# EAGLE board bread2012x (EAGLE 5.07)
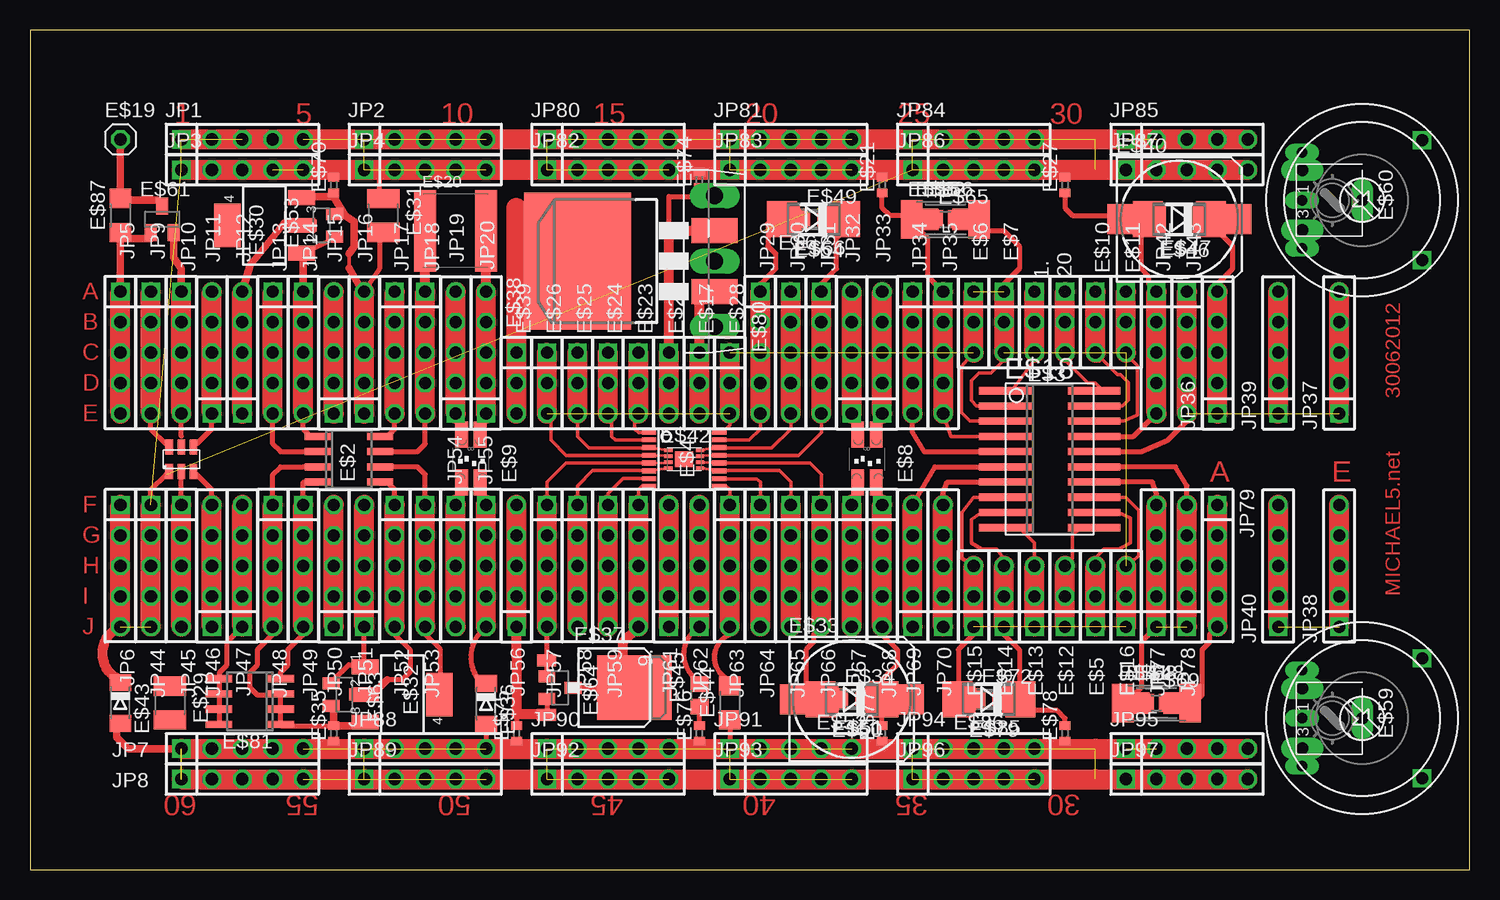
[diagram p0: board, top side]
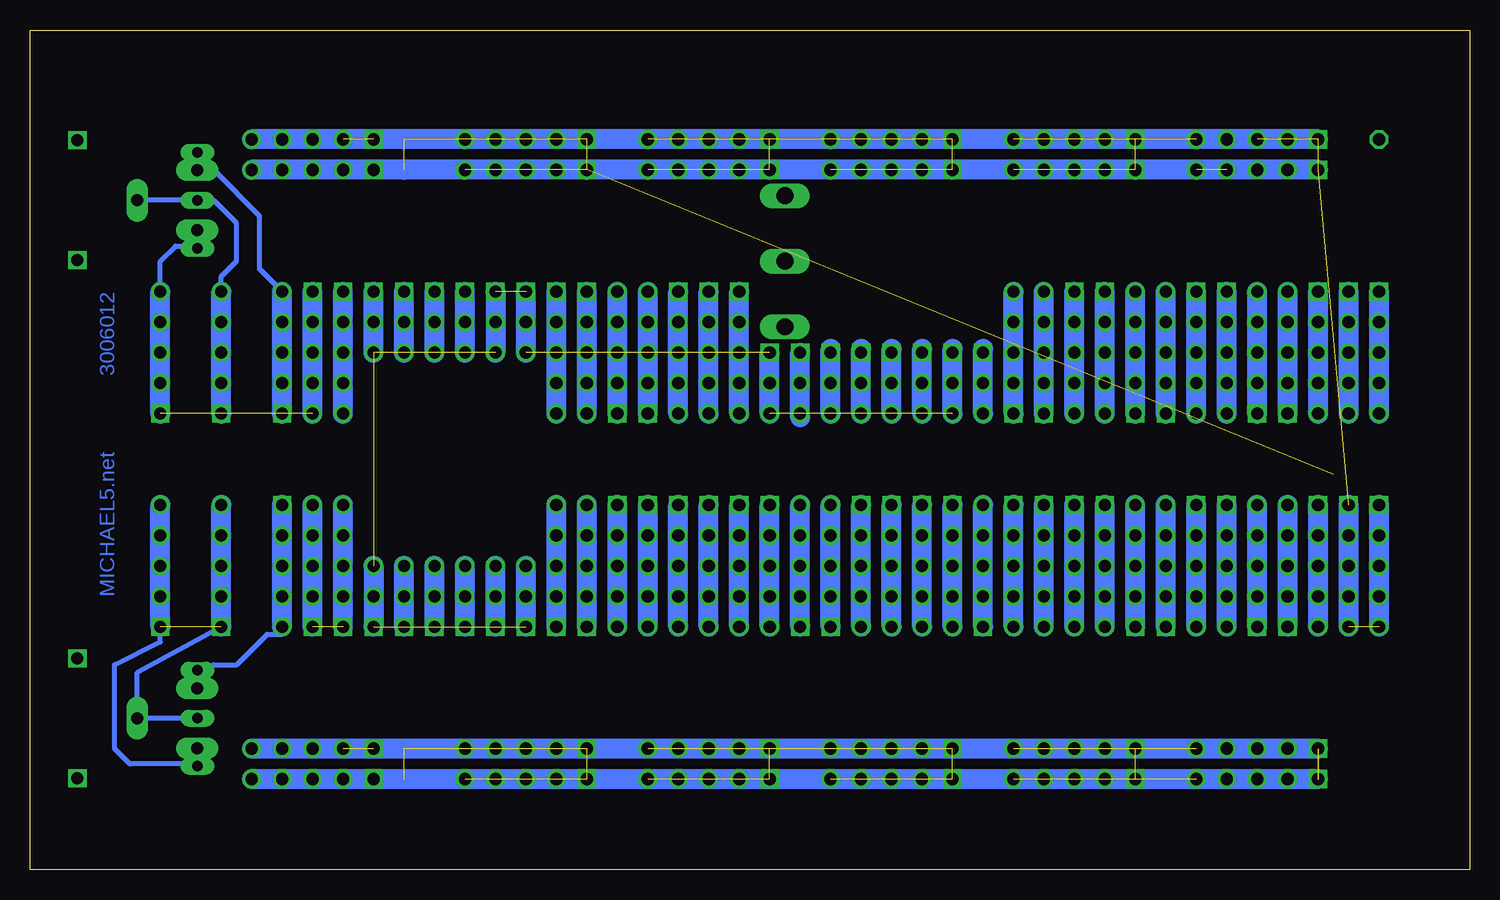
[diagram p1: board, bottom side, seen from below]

Size 120 x 70 mm. Coordinates in mm from the lower left corner, seen from the top.
Outline: 0,0 120,0 120,70 0,70 0,0
Copper layers (1*16): Top 0.035mm / dielectric 1.5mm / Bottom 0.035mm
Design rules "default": minimum track width 10mil, minimum drill 24mil, track to track 8mil, track to pad 8mil, pad to pad 8mil, via to via 8mil, smd to smd 8mil, copper to edge 40mil, drill to drill 8mil, minimum pad ring 10mil, minimum via ring 8mil, stop-mask expansion 4mil, vias tented up to drill 0mil, thermal gap 10mil

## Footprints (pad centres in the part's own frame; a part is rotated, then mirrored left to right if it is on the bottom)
1X03 = drill 1.016 square: 1 -2.54,0 | drill 1.016 octagon: 2 0,0; 3 2.54,0
1X05 = drill 1.016 square: 1 -5.08,0 | drill 1.016 octagon: 2 -2.54,0; 3 0,0; 4 2.54,0; 5 5.08,0
SOT23-6 = smd 0.635 x 1.27: 1 -1.016,-1.016; 2 0,-1.016; 3 1.016,-1.016; 4 1.016,1.016; 5 0,1.016; 6 -1.016,1.016
SO08 = smd 0.6 x 2.2: 1 -1.905,-2.6; 2 -0.635,-2.6; 3 0.635,-2.6; 4 1.905,-2.6; 5 1.905,2.6; 6 0.635,2.6; 7 -0.635,2.6; 8 -1.905,2.6
SO-20 = smd 0.6 x 2.2: 1 -5.715,-2.6; 2 -4.445,-2.6; 3 -3.175,-2.6; 4 -1.905,-2.6; 5 -0.635,-2.6; 6 0.635,-2.6; 7 1.905,-2.6; 8 3.175,-2.6; 9 4.445,-2.6; 10 5.715,-2.6; 11 5.715,2.6; 12 4.445,2.6; 13 3.175,2.6; 14 1.905,2.6; 15 0.635,2.6; 16 -0.635,2.6; 17 -1.905,2.6; 18 -3.175,2.6; 19 -4.445,2.6; 20 -5.715,2.6
SSOP16 = smd 0.4 x 1.2: 1 -2.275,-2.925; 2 -1.625,-2.925; 3 -0.975,-2.925; 4 -0.325,-2.925; 5 0.325,-2.925; 6 0.975,-2.925; 7 1.625,-2.925; 8 2.275,-2.925; 9 2.275,2.925; 10 1.625,2.925; 11 0.975,2.925; 12 0.325,2.925; 13 -0.325,2.925; 14 -0.975,2.925; 15 -1.625,2.925; 16 -2.275,2.925
DUOLEDSMD = smd 1.067 x 2.184: AGRN 0.77,1.95; ARED -0.77,1.95; CGRN 0.77,-2.05; CRED -0.77,-2.05
SO-20WL = smd 0.6 x 2.2: 1 -5.715,-4.788; 2 -4.445,-4.788; 3 -3.175,-4.788; 4 -1.905,-4.788; 5 -0.635,-4.788; 6 0.635,-4.788; 7 1.905,-4.788; 8 3.175,-4.788; 9 4.445,-4.788; 10 5.715,-4.788; 11 5.715,4.788; 12 4.445,4.788; 13 3.175,4.788; 14 1.905,4.788; 15 0.635,4.788; 16 -0.635,4.788; 17 -1.905,4.788; 18 -3.175,4.788; 19 -4.445,4.788; 20 -5.715,4.788
1X01 = drill 1.016 octagon: 1 0,0
C2225K = smd 1.85 x 6.8: 1 -2.55,0; 2 2.55,0
R0402 = smd 0.7 x 0.9: 1 -0.65,0; 2 0.65,0
R1210 = smd 1.6 x 2.7: 1 -1.4,0; 2 1.4,0
SOT223 = smd 1.219 x 2.235: 1 -2.311,-3.099; 2 0,-3.099; 3 2.311,-3.099 | smd 3.6 x 2.2: 4 0,3.099
153CLV-1010 = smd 4 x 2.5: + 4,0; - -4,0
R0805 = smd 1.3 x 1.5: 1 -0.95,0; 2 0.95,0
MINIMELF = smd 1.4 x 1.8: A 1.7,0; C -1.7,0
D-PAK_TO252AA = smd 1 x 1.6: 1 -2.28,-4.8; 3 2.28,-4.8 | smd 5.4 x 6.2: 4 0,2.5
D2PACK = smd 2.083 x 3.81: 1 -2.54,-8.89; 3 2.54,-8.89 | smd 11.43 x 8.89: 2 0,2.54
R5025W = smd 2 x 1.8: 1 -2.311,0; 2 2.311,0
DFN-2X3 = smd 0.7 x 0.3: 1 -1.325,0.75; 2 -1.325,0.25; 3 -1.325,-0.25; 4 -1.325,-0.75; 5 1.325,-0.75; 6 1.325,-0.25; 7 1.325,0.25; 8 1.325,0.75 | smd 1.5 x 1.3: EXP 0,0
R1206 = smd 1.6 x 1.803: 1 -1.422,0; 2 1.422,0
DO-214AC = smd 1.8 x 2.4: A 2.025,0; C -2.025,0
MELF-MLL41 = smd 2.5 x 3: A 2.625,0; C -2.625,0
R3225W = smd 1.8 x 1.8: 1 -1.499,0; 2 1.499,0
SOT23 = smd 1 x 1.4: 1 -0.95,-1.1; 2 0.95,-1.1; 3 0,1.1
RANDL = drill 0.9 long: A -4,5; E 4,5; S 0,5 | drill 1 square: P$1 -5,-5; P$2 5,-5
EVND8AA = drill 1 pad 1.778 long: A -2.5,-2.5; E 2.5,-2.5; S 0,2.5
R2512 = smd 1.8 x 3.2: 1 -2.8,0; 2 2.8,0
R2012 = smd 1.3 x 1.5: 1 -0.85,0; 2 0.85,0
SOT93V = drill 1.397 long: B -5.461,-2.54; C 0,-2.54; E 5.461,-2.54
SO-08 = smd 0.6 x 2.2: 1 -1.905,-2.6; 2 -0.635,-2.6; 3 0.635,-2.6; 4 1.905,-2.6; 5 1.905,2.6; 6 0.635,2.6; 7 -0.635,2.6; 8 -1.905,2.6

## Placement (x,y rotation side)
1.  [1X03]  83.74,45.64 270 top
9.  [1X05]  50.72,25.32 270 top
20  [1X03]  86.28,45.64 270 top
E$1  [SOT23-6]  12.62,34.21 0 top
E$2  [SO08]  26.59,34.21 270 top
E$3  [SO-20]  85.01,34.21 270 top
E$4  [SSOP16]  54.53,34.21 270 top
E$5  [1X03]  88.82,22.78 90 top
E$6  [1X03]  78.66,45.64 270 top
E$7  [1X03]  81.2,45.64 270 top
E$8  [DUOLEDSMD]  69.77,34.21 180 top
E$9  [DUOLEDSMD]  36.75,34.21 180 top
E$10  [1X03]  88.82,45.64 270 top
E$11  [1X03]  91.36,45.64 270 top
E$12  [1X03]  86.28,22.78 90 top
E$13  [1X03]  83.74,22.78 90 top
E$14  [1X03]  81.2,22.78 90 top
E$15  [1X03]  78.66,22.78 90 top
E$16  [1X03]  91.36,22.78 90 top
E$17  [1X03]  55.8,40.56 270 top
E$18  [SO-20WL]  85.01,34.21 270 top
E$19  [1X01]  7.54,60.88 0 top
E$20  [C2225K]  35.48,53.26 0 top
E$21  [R0402]  71.04,57.07 90 top
E$22  [1X03]  53.26,40.56 270 top
E$23  [1X03]  50.72,40.56 270 top
E$24  [1X03]  48.18,40.56 270 top
E$25  [1X03]  45.64,40.56 270 top
E$26  [1X03]  43.1,40.56 270 top
E$27  [R0402]  86.28,57.07 90 top
E$28  [1X03]  58.34,40.56 270 top
E$29  [R1210]  11.67,13.89 270 top
E$30  [SOT223]  19.54,53.7 90 top
E$31  [R1210]  29.45,54.53 270 top
E$32  [SOT223]  31.04,14.59 270 top
E$33  [153CLV-1010]  68.5,14.21 0 top
E$34  [R0805]  68.5,14.21 0 top
E$35  [R0402]  25.32,11.35 90 top
E$36  [MINIMELF]  38.02,13.83 270 top
E$37  [D-PAK_TO252AA]  47.86,15.16 270 top
E$38  [D2PACK]  48.18,50.72 90 top
E$39  [1X03]  40.56,40.56 270 top
E$40  [153CLV-1010]  95.81,54.21 0 top
E$41  [R5025W]  93.9,13.89 0 top
E$42  [DFN-2X3]  54.53,34.21 0 top
E$43  [MINIMELF]  7.54,13.89 270 top
E$44  [R1206]  58.34,13.89 90 top
E$45  [R0805]  55.8,14.53 90 top
E$46  [DO-214AC]  95.81,54.21 180 top
E$47  [MELF-MLL41]  95.81,54.21 180 top
E$48  [R3225W]  93.9,13.89 0 top
E$49  [R0805]  65.33,54.21 0 top
E$50  [DO-214AC]  68.5,14.21 180 top
E$51  [MELF-MLL41]  68.5,14.21 180 top
E$52  [R1206]  68.5,14.21 180 top
E$53  [SOT23]  24.3,53.7 90 top
E$54  [DO-214AC]  65.33,54.21 180 top
E$55  [R5025W]  76.31,54.21 0 top
E$56  [R3225W]  76.31,54.21 0 top
E$57  [RANDL]  111.05,55.8 90 top
E$58  [RANDL]  111.05,12.62 90 top
E$59  [EVND8AA]  108.56,12.62 270 top
E$60  [EVND8AA]  108.56,55.8 270 top
E$61  [SOT23]  11.03,54.21 0 top
E$62  [R2512]  76.31,54.21 0 top
E$63  [SOT23]  26.21,14.59 270 top
E$64  [SOT23]  44.18,15.16 270 top
E$65  [R2012]  76.31,54.21 0 top
E$66  [MELF-MLL41]  65.33,54.21 180 top
E$67  [R1206]  65.33,54.21 180 top
E$68  [R2512]  93.9,13.89 0 top
E$69  [R2012]  93.9,13.89 0 top
E$70  [R0402]  25.32,57.07 90 top
E$72  [R0805]  79.93,14.21 0 top
E$74  [R0402]  55.8,57.51 90 top
E$75  [R0402]  40.56,11.35 90 top
E$76  [R0402]  55.8,11.35 90 top
E$77  [R0402]  71.04,11.35 90 top
E$78  [R0402]  86.28,11.35 90 top
E$79  [DO-214AC]  79.93,14.21 180 top
E$80  [SOT93V]  54.53,50.72 90 top
E$81  [SO-08]  18.34,14.02 90 top
E$85  [MELF-MLL41]  79.93,14.21 180 top
E$86  [R1206]  79.93,14.21 180 top
E$87  [R1206]  7.54,54.53 90 top
JP1  [1X05]  17.7,60.88 0 top
JP2  [1X05]  32.94,60.88 0 top
JP3  [1X05]  17.7,58.34 0 top
JP4  [1X05]  32.94,58.34 0 top
JP5  [1X05]  7.54,43.1 270 top
JP6  [1X05]  7.54,25.32 270 top
JP7  [1X05]  17.7,10.08 0 top
JP8  [1X05]  17.7,7.54 0 top
JP9  [1X05]  10.08,43.1 270 top
JP10  [1X05]  12.62,43.1 270 top
JP11  [1X05]  15.16,43.1 90 top
JP12  [1X05]  17.7,43.1 90 top
JP13  [1X05]  20.24,43.1 270 top
JP14  [1X05]  22.78,43.1 270 top
JP15  [1X05]  25.32,43.1 90 top
JP16  [1X05]  27.86,43.1 90 top
JP17  [1X05]  30.4,43.1 270 top
JP18  [1X05]  32.94,43.1 270 top
JP19  [1X05]  35.48,43.1 90 top
JP20  [1X05]  38.02,43.1 90 top
JP29  [1X05]  60.88,43.1 270 top
JP30  [1X05]  63.42,43.1 270 top
JP31  [1X05]  65.96,43.1 270 top
JP32  [1X05]  68.5,43.1 90 top
JP33  [1X05]  71.04,43.1 90 top
JP34  [1X05]  73.58,43.1 270 top
JP35  [1X05]  76.12,43.1 270 top
JP36  [1X05]  98.98,43.1 90 top
JP37  [1X05]  109.14,43.1 90 top
JP38  [1X05]  109.14,25.32 90 top
JP39  [1X05]  104.06,43.1 90 top
JP40  [1X05]  104.06,25.32 90 top
JP42  [1X05]  93.9,43.1 270 top
JP43  [1X05]  96.44,43.1 270 top
JP44  [1X05]  10.08,25.32 270 top
JP45  [1X05]  12.62,25.32 270 top
JP46  [1X05]  15.16,25.32 90 top
JP47  [1X05]  17.7,25.32 90 top
JP48  [1X05]  20.24,25.32 270 top
JP49  [1X05]  22.78,25.32 270 top
JP50  [1X05]  25.32,25.32 90 top
JP51  [1X05]  27.86,25.32 90 top
JP52  [1X05]  30.4,25.32 270 top
JP53  [1X05]  32.94,25.32 270 top
JP54  [1X05]  35.48,25.32 270 top
JP55  [1X05]  38.02,25.32 270 top
JP56  [1X05]  40.56,25.32 90 top
JP57  [1X05]  43.1,25.32 270 top
JP58  [1X05]  45.64,25.32 270 top
JP59  [1X05]  48.18,25.32 270 top
JP61  [1X05]  53.26,25.32 90 top
JP62  [1X05]  55.8,25.32 90 top
JP63  [1X05]  58.34,25.32 270 top
JP64  [1X05]  60.88,25.32 270 top
JP65  [1X05]  63.42,25.32 270 top
JP66  [1X05]  65.96,25.32 270 top
JP67  [1X05]  68.5,25.32 270 top
JP68  [1X05]  71.04,25.32 270 top
JP69  [1X05]  73.58,25.32 90 top
JP70  [1X05]  76.12,25.32 90 top
JP77  [1X05]  93.9,25.32 90 top
JP78  [1X05]  96.44,25.32 90 top
JP79  [1X05]  98.98,25.32 270 top
JP80  [1X05]  48.18,60.88 0 top
JP81  [1X05]  63.42,60.88 0 top
JP82  [1X05]  48.18,58.34 0 top
JP83  [1X05]  63.42,58.34 0 top
JP84  [1X05]  78.66,60.88 0 top
JP85  [1X05]  96.44,60.88 0 top
JP86  [1X05]  78.66,58.34 0 top
JP87  [1X05]  96.44,58.34 0 top
JP88  [1X05]  32.94,10.08 0 top
JP89  [1X05]  32.94,7.54 0 top
JP90  [1X05]  48.18,10.08 0 top
JP91  [1X05]  63.42,10.08 0 top
JP92  [1X05]  48.18,7.54 0 top
JP93  [1X05]  63.42,7.54 0 top
JP94  [1X05]  78.66,10.08 0 top
JP95  [1X05]  96.44,10.08 0 top
JP96  [1X05]  78.66,7.54 0 top
JP97  [1X05]  96.44,7.54 0 top

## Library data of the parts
1. 9. 20 E$5-E$7 E$10-E$17 E$22-E$26 E$28 E$39 JP1-JP20 JP29-JP40 JP42-JP59 JP61-JP70 JP77-JP97 = pinhead(2)
E$1 = microchip-5
E$2 E$4 = linear
E$3 E$18 E$42 = microchip
E$8 E$9 = led
E$19 = pinhead
E$20 E$21 E$27 E$29 E$31 E$33-E$35 E$40 E$41 E$44 E$45 E$48 E$49 E$52 E$55 E$56 E$62 E$65 E$67-E$70 E$72 E$74-E$78 E$86 E$87 = rcl
E$30 E$32 E$53 E$61 E$63 E$64 = transistor-npn
E$36 E$43 E$46 E$47 E$50 E$51 E$54 E$66 E$79 E$85 = diode
E$37 E$38 E$80 E$81 = transistor-power
E$57-E$60 = pot

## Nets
N$1: JP1.1 JP1.2 JP1.3
N$2: JP2.1 JP2.2
N$3: JP3.4 JP3.5
N$76: JP80.1 JP80.2 JP80.3
N$77: JP81.1 JP81.2
N$78: JP82.4 JP82.5
N$80: JP84.1 JP84.2 JP84.3
N$81: JP85.1 JP85.2
N$82: JP86.4 JP86.5
N$84: JP88.1 JP88.2
N$86: JP90.1 JP90.2 JP90.3
N$87: JP91.1 JP91.2
N$88: JP92.4 JP92.5
N$90: JP94.1 JP94.2 JP94.3
N$91: JP95.1 JP95.2
N$92: JP96.4 JP96.5
S$30: E$7.3
S$43: E$14.3
S$45: E$17.1
S$57: E$19.1

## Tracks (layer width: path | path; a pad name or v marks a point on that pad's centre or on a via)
N$1  (2 unrouted)
N$2  (1 unrouted)
N$3  (1 unrouted)
N$4
  Top 1.676: 7.54,38.02 7.54,48.18
N$5
  Top 0.406: 11.35,35.48 10.08,36.75 10.08,38.02
  Top 1.676: 10.08,38.02 10.08,48.18
N$6
  Top 0.406: 12.62,36.11 12.62,38.02
  Top 1.676: 12.62,38.02 12.62,48.18
N$7  (1 unrouted)
  Top 1.676: 109.14,38.02 109.14,48.18 | 104.06,38.02 104.06,48.18
N$8
  Top 1.676: 93.9,38.02 93.9,48.18
N$15
  Top 0.305: 76.44,42.15 76.12,42.47 76.12,43.1 | 79.3,36.11 76.75,36.11 76.12,38.02
  Top 0.406: 76.75,39.29 76.44,42.15 | 76.12,48.18 74.85,49.45 74.85,52.62 73.58,53.9 73.58,54.53 71.67,54.53 71.04,55.16 71.04,56.44
  Top 1.676: 76.12,38.02 76.12,43.1 76.12,48.18
N$19
  Top 0.406: 65.96,48.18 65.96,48.81 67.23,50.09 67.23,52.62 67.87,53.26 67.87,54.53
  Top 1.676: 65.96,38.02 65.96,48.18
N$20
  Top 0.305: 57.7,35.16 61.83,35.16 63.42,36.75 63.42,38.02
  Top 1.676: 63.42,38.02 63.42,48.18
N$21
  Top 0.305: 57.7,35.8 59.93,35.8 60.88,36.75 60.88,38.02
  Top 0.406: 61.52,53.9 61.52,51.99 62.15,51.35 62.15,50.09 60.88,48.81 60.88,46.91
  Top 1.676: 60.88,38.02 60.88,46.91 60.88,48.18
N$25
  Top 0.305: 51.04,36.43 50.72,36.43 50.4,36.75 50.4,37.7 50.72,38.02
N$26
  Top 0.305: 51.04,35.8 48.81,35.8 48.5,36.11 48.5,37.7 48.18,38.02
N$27
  Top 0.305: 51.04,35.16 46.59,35.16 45.64,36.11 45.64,38.02
N$28
  Top 0.305: 51.35,34.53 44.69,34.53 43.42,35.8 43.42,37.7 43.1,38.02
N$29
  Top 1.676: 40.56,38.02 40.56,55.16
N$30
  Top 0.813: 38.02,48.18 38.02,50.72
  Top 1.676: 38.02,38.02 38.02,48.18
N$31
  Top 1.676: 35.48,38.02 35.48,48.18
N$32
  Top 0.406: 29.77,34.84 32.3,34.84 32.94,35.48 32.94,38.02
  Top 0.813: 32.94,48.18 32.94,51.04
  Top 1.676: 32.94,38.02 32.94,48.18
N$33
  Top 0.406: 29.77,36.11 30.4,36.75 30.4,38.02
  Top 1.676: 30.4,38.02 30.4,48.18
N$34
  Top 0.305: 26.59,50.15 26.59,51.35
  Top 0.406: 29.13,52.62 29.13,50.09 27.86,48.18
  Top 0.61: 22.46,56.12 25.32,56.12 26.27,54.53 27.04,54.02 27.04,51.93 26.59,51.35 | 26.59,50.15 27.54,48.5 27.86,48.18
  Top 1.676: 27.86,38.02 27.86,48.18
N$35
  Top 1.676: 25.32,38.02 25.32,48.18
N$36
  Top 0.406: 23.41,36.11 22.78,36.75 22.78,38.02
  Top 1.676: 22.78,38.02 22.78,48.18
N$37
  Top 0.406: 23.41,34.84 20.88,34.84 20.24,35.48 20.24,38.02
  Top 1.676: 20.24,38.02 20.24,48.18
N$38
  Top 0.61: 22.14,53.9 21.19,53.9 18.34,50.4 17.7,48.18
  Top 1.676: 17.7,38.02 17.7,48.18
N$39
  Top 0.406: 13.89,35.48 15.16,36.75 15.16,38.02
  Top 1.676: 15.16,38.02 15.16,48.18
N$40  (4 unrouted)
  Top 0.406: 11.35,32.94 10.08,31.67 10.08,30.4
  Top 1.676: 88.82,58.34 101.52,58.34 | 88.82,60.88 101.52,60.88 | 73.58,60.88 83.74,60.88 | 73.58,58.34 83.74,58.34 | 10.08,20.24 10.08,30.4
N$41
  Top 0.406: 97.08,13.89 97.71,14.53 97.71,18.34 98.34,18.97 98.34,19.61 98.98,20.24
  Top 1.676: 98.98,20.24 98.98,30.4
N$42
  Top 0.406: 90.41,33.58 95.49,33.58 96.44,31.99 96.44,30.08
  Top 1.676: 96.44,30.4 96.44,30.08 96.44,20.24
N$43
  Top 0.406: 90.41,32.3 93.58,32.3 93.9,31.35 93.9,30.4
  Top 1.676: 93.9,20.24 93.9,30.4
N$49
  Top 0.813: 7.54,15.79 arc-136 7.54,20.24
N$50
  Top 0.305: 76.12,30.4 76.12,30.72
  Top 0.406: 79.93,32.3 76.44,32.3 76.12,31.35 76.12,30.72
  Top 1.676: 76.12,20.24 76.12,30.4
N$51
  Top 0.406: 79.93,33.58 75.42,33.58 73.58,30.4
  Top 1.676: 73.58,20.24 73.58,30.4
N$52
  Top 0.406: 71.04,20.24 71.04,19.61 72.31,18.34 72.31,17.06 71.04,15.79 71.04,14.53
  Top 1.676: 71.04,20.24 71.04,30.4
N$53
  Top 1.676: 68.5,20.24 68.5,30.4
N$54
  Top 1.676: 65.96,20.24 65.96,30.4
N$55
  Top 0.305: 57.39,33.26 62.47,33.26 63.42,32.3 63.42,30.4
  Top 1.676: 63.42,20.24 63.42,30.4
N$56
  Top 0.305: 57.7,32.56 60.56,32.56 60.88,32.3 60.88,30.4
  Top 1.676: 60.88,20.24 60.88,30.4
N$57
  Top 0.305: 58.02,31.99 58.34,31.67 58.34,30.08
  Top 1.676: 58.34,20.24 58.34,30.08 58.34,30.4
N$58
  Top 0.406: 55.93,15.6 arc-121 55.8,20.24
  Top 1.676: 55.8,20.24 55.8,30.4
N$59
  Top 1.676: 53.26,20.24 53.26,30.4
N$60
  Top 0.305: 51.35,31.99 51.04,31.99 50.72,31.67 50.72,30.4
  Top 0.406: 45.64,15.16 49.45,15.16
  Top 0.813: 49.45,15.16 49.45,18.97 50.72,20.24
  Top 1.676: 50.72,20.24 50.72,30.4
N$61
  Top 0.305: 51.04,32.62 49.45,32.62 48.18,31.35 48.18,30.4
  Top 1.676: 48.18,20.24 48.18,30.4
N$62
  Top 0.305: 51.04,33.26 46.91,33.26 45.64,31.99 45.64,30.4
  Top 1.676: 45.64,20.24 45.64,30.4
N$63
  Top 0.305: 51.04,33.89 44.69,33.89 43.1,32.3 43.1,30.4
  Top 0.406: 43.1,17.7 43.1,20.24
  Top 1.676: 43.1,20.24 43.1,30.4
N$64
  Top 1.676: 40.56,20.24 40.56,30.4
N$65
  Top 0.406: 38.02,20.24 arc106 38.02,15.16
  Top 1.676: 38.02,20.24 38.02,30.4
N$66
  Top 1.676: 35.48,20.24 35.48,30.4
N$67
  Top 0.406: 29.77,33.58 32.3,33.58 32.94,32.94 32.94,30.4 | 34.21,16.43 34.21,18.34 32.94,19.61 32.94,20.24
  Top 1.676: 32.94,20.24 32.94,30.4
N$68
  Top 0.406: 29.77,32.3 30.4,31.67 30.4,30.4
  Top 1.676: 30.4,20.24 30.4,30.4
N$69
  Top 0.406: 25.32,15.79 26.59,17.06 27.86,17.06 27.86,20.24
  Top 1.676: 27.86,20.24 27.86,30.4
N$70
  Top 1.676: 25.32,20.24 25.32,30.4
N$71
  Top 0.406: 22.78,30.4 22.78,32.3 | 20.88,15.79 20.88,16.43 21.51,17.06 21.51,18.34 22.78,19.61 22.78,20.24
  Top 1.676: 22.78,20.24 22.78,30.4
N$72
  Top 0.406: 22.78,33.58 20.88,33.58 20.24,32.94 20.24,30.4 | 20.24,14.53 18.97,14.53 18.34,15.16 18.34,16.43 18.97,17.06 18.97,18.34 20.24,19.61 20.24,20.24
  Top 1.676: 20.24,20.24 20.24,30.4
N$73
  Top 0.406: 15.79,11.98 15.79,16.43 16.43,17.06 16.43,18.97 17.7,20.24
  Top 1.676: 17.7,20.24 17.7,30.4
N$74
  Top 0.406: 13.89,32.94 15.16,31.67 15.16,30.4
  Top 1.676: 15.16,20.24 15.16,30.4
N$75
  Top 0.406: 12.62,30.4 12.62,32.94
  Top 1.676: 12.62,20.24 12.62,30.4
N$76  (2 unrouted)
N$77  (1 unrouted)
N$78  (1 unrouted)
N$79  (3 unrouted)
  Top 1.676: 58.34,60.88 68.5,60.88 | 58.34,58.34 68.5,58.34 | 43.1,58.34 53.26,58.34 | 43.1,60.88 53.26,60.88
N$80  (2 unrouted)
N$81  (1 unrouted)
N$82  (1 unrouted)
N$83  (3 unrouted)
  Top 0.406: 29.13,56.44 29.13,58.34
  Top 1.676: 27.86,60.88 38.02,60.88 | 27.86,58.34 29.13,58.34 38.02,58.34 | 12.62,58.34 22.78,58.34 | 12.62,60.88 22.78,60.88
N$84  (1 unrouted)
N$85  (3 unrouted)
  Top 1.676: 73.58,7.54 83.74,7.54 | 73.58,10.08 83.74,10.08 | 88.82,10.08 101.52,10.08 | 88.82,7.54 101.52,7.54
N$86  (2 unrouted)
N$87  (1 unrouted)
N$88  (1 unrouted)
N$89  (3 unrouted)
  Top 1.676: 58.34,10.08 68.5,10.08 | 58.34,7.54 68.5,7.54 | 43.1,7.54 53.26,7.54 | 43.1,10.08 53.26,10.08
N$90  (2 unrouted)
N$91  (1 unrouted)
N$92  (1 unrouted)
N$94
  Bottom 1.676: 7.54,38.02 7.54,48.18
N$95
  Bottom 1.676: 10.08,38.02 10.08,48.18
N$96
  Bottom 1.676: 12.62,38.02 12.62,48.18
N$97
  Bottom 1.676: 15.16,38.02 15.16,48.18
N$98
  Bottom 1.676: 17.7,38.02 17.7,48.18
N$99
  Bottom 1.676: 20.24,38.02 20.24,48.18
N$100
  Bottom 1.676: 22.78,38.02 22.78,48.18
N$101
  Bottom 1.676: 25.32,38.02 25.32,48.18
N$102
  Bottom 1.676: 27.86,38.02 27.86,48.18
N$103
  Bottom 1.676: 30.4,38.02 30.4,48.18
N$104
  Bottom 1.676: 32.94,38.02 32.94,48.18
N$105
  Bottom 1.676: 35.48,38.02 35.48,48.18
N$106
  Bottom 1.676: 38.02,38.02 38.02,48.18
N$107
  Bottom 1.676: 40.56,38.02 40.56,43.42
N$108
  Bottom 1.676: 43.1,38.02 43.1,43.42
N$109
  Bottom 1.676: 45.64,38.02 45.64,43.42
N$110
  Bottom 1.676: 48.18,38.02 48.18,43.42
N$111
  Bottom 1.676: 50.72,38.02 50.72,43.42
N$112
  Bottom 1.676: 53.26,38.02 53.26,43.42
N$113
  Bottom 1.676: 55.8,37.7 55.8,43.1
N$114
  Bottom 1.676: 58.34,38.02 58.34,43.04
N$115
  Bottom 1.676: 60.88,38.02 60.88,48.18
N$116
  Bottom 1.676: 63.42,38.02 63.42,48.18
N$117
  Bottom 1.676: 65.96,38.02 65.96,48.18
N$118
  Bottom 1.676: 68.5,38.02 68.5,48.18
N$119
  Bottom 1.676: 71.04,38.02 71.04,48.18
N$120
  Bottom 1.676: 73.58,38.02 73.58,48.18
N$121
  Bottom 1.676: 76.12,38.02 76.12,48.18
N$126
  Top 0.406: 40.56,12.94 40.56,11.98
  Top 0.813: 40.56,20.24 40.56,17.7 40.56,12.94 42.34,12.94
N$128
  Bottom 1.676: 93.9,38.02 93.9,48.18
N$130  (5 unrouted)
  Bottom 1.676: 10.08,20.24 10.08,30.4 | 12.62,60.88 22.78,60.88 | 12.62,58.34 22.78,58.34 | 27.86,58.34 38.02,58.34 | 27.86,60.88 38.02,60.88 | 7.54,20.24 7.54,30.4
N$131
  Bottom 1.676: 12.62,20.24 12.62,30.4
N$132
  Bottom 1.676: 15.16,20.24 15.16,30.4
N$133
  Bottom 1.676: 17.7,20.24 17.7,30.4
N$134
  Bottom 1.676: 20.24,20.24 20.24,30.4
N$135
  Bottom 1.676: 22.78,20.24 22.78,30.4
N$136
  Bottom 1.676: 25.32,20.24 25.32,30.4
N$137
  Bottom 1.676: 27.86,20.24 27.86,30.4
N$138
  Bottom 1.676: 30.4,20.24 30.4,30.4
N$139
  Bottom 1.676: 32.94,20.24 32.94,30.4
N$140
  Bottom 1.676: 35.48,20.24 35.48,30.4
N$141
  Bottom 1.676: 38.02,20.24 38.02,30.4
N$142
  Bottom 1.676: 40.56,20.24 40.56,30.4
N$143
  Bottom 1.676: 43.1,20.24 43.1,30.4
N$144
  Bottom 1.676: 45.64,20.24 45.64,30.4
N$145
  Bottom 1.676: 48.18,20.24 48.18,30.4
N$146
  Bottom 1.676: 50.72,20.24 50.72,30.4
N$147
  Bottom 1.676: 53.26,20.24 53.26,30.4
N$148
  Bottom 1.676: 55.8,20.24 55.8,30.4
N$149
  Bottom 1.676: 58.34,20.24 58.34,30.4
N$150
  Bottom 1.676: 60.88,20.24 60.88,30.4
N$151
  Bottom 1.676: 63.42,20.24 63.42,30.4
N$152
  Bottom 1.676: 65.96,20.24 65.96,30.4
N$153
  Bottom 1.676: 68.5,20.24 68.5,30.4
N$154
  Bottom 1.676: 71.04,20.24 71.04,30.4
N$155
  Bottom 1.676: 73.58,20.24 73.58,30.4
N$156
  Bottom 1.676: 76.12,20.24 76.12,30.4
N$164  (1 unrouted)
  Bottom 1.676: 96.44,20.24 96.44,30.4 | 93.9,20.24 93.9,30.4
N$165
  Bottom 0.406: 98.98,20.24 98.98,19.61 100.25,19.61 102.79,17.06 104.69,17.06 105.97,16.43
  Bottom 1.676: 98.98,20.24 98.98,30.4
N$166  (3 unrouted)
  Bottom 1.676: 43.1,60.88 53.26,60.88 | 43.1,58.34 53.26,58.34 | 58.34,58.34 68.5,58.34 | 58.34,60.88 68.5,60.88
N$167  (3 unrouted)
  Bottom 1.676: 73.58,60.88 83.74,60.88 | 73.58,58.34 83.74,58.34 | 88.82,58.34 101.52,58.34 | 88.82,60.88 101.52,60.88
N$168  (3 unrouted)
  Bottom 1.676: 27.86,7.54 38.02,7.54 | 27.86,10.08 38.02,10.08 | 12.62,10.08 22.78,10.08 | 12.62,7.54 22.78,7.54
N$169  (3 unrouted)
  Bottom 1.676: 43.1,10.08 53.26,10.08 | 43.1,7.54 53.26,7.54 | 58.34,7.54 68.5,7.54 | 58.34,10.08 68.5,10.08
N$170  (3 unrouted)
  Bottom 1.676: 73.58,10.08 83.74,10.08 | 73.58,7.54 83.74,7.54 | 88.82,7.54 101.52,7.54 | 88.82,10.08 101.52,10.08
N$191  (1 unrouted)
  Top 1.676: 104.06,20.24 104.06,30.4 | 109.14,20.24 109.14,30.4
N$192
  Bottom 0.406: 109.14,20.24 109.14,18.97 112.95,17.06 112.95,10.08 111.68,8.81 106.6,8.81
  Bottom 1.676: 109.14,20.24 109.14,30.4
N$193
  Top 0.406: 44.37,54.53 45.01,54.53 45.64,53.9 45.64,51.35
N$194
  Top 0.406: 43.1,48.18 43.1,51.99
S$1
  Top 1.676: 83.74,60.88 88.82,60.88
S$2
  Top 1.676: 83.74,58.34 88.82,58.34
S$3  (1 unrouted)
  Top 1.676: 53.26,60.88 58.34,60.88 | 68.5,60.88 73.58,60.88
S$4  (1 unrouted)
  Top 1.676: 53.26,58.34 58.34,58.34 | 68.5,58.34 73.58,58.34
S$5  (1 unrouted)
  Top 1.676: 22.78,60.88 27.86,60.88 | 38.02,60.88 43.1,60.88
S$6  (1 unrouted)
  Top 1.676: 22.78,58.34 27.86,58.34 | 38.02,58.34 43.1,58.34
S$7
  Top 1.676: 83.74,10.08 88.82,10.08
S$8
  Top 1.676: 83.74,7.54 88.82,7.54
S$9  (1 unrouted)
  Top 1.676: 53.26,10.08 58.34,10.08 | 68.5,10.08 73.58,10.08
S$10  (1 unrouted)
  Top 1.676: 53.26,7.54 58.34,7.54 | 68.5,7.54 73.58,7.54
S$11  (1 unrouted)
  Top 1.676: 22.78,10.08 27.86,10.08 | 38.02,10.08 43.1,10.08
S$12  (1 unrouted)
  Top 1.676: 22.78,7.54 27.86,7.54 | 38.02,7.54 43.1,7.54
S$13
  Bottom 1.676: 22.78,60.88 27.86,60.88
S$14
  Bottom 1.676: 22.78,58.34 27.86,58.34
S$15  (1 unrouted)
  Bottom 1.676: 53.26,60.88 58.34,60.88 | 38.02,60.88 43.1,60.88
S$16  (1 unrouted)
  Bottom 1.676: 53.26,58.34 58.34,58.34 | 38.02,58.34 43.1,58.34
S$17  (1 unrouted)
  Bottom 1.676: 83.74,60.88 88.82,60.88 | 68.5,60.88 73.58,60.88
S$18  (1 unrouted)
  Bottom 1.676: 83.74,58.34 88.82,58.34 | 68.5,58.34 73.58,58.34
S$19
  Bottom 1.676: 22.78,10.08 27.86,10.08
S$20
  Bottom 1.676: 22.78,7.54 27.86,7.54
S$21  (1 unrouted)
  Bottom 1.676: 53.26,10.08 58.34,10.08 | 38.02,10.08 43.1,10.08
S$22  (1 unrouted)
  Bottom 1.676: 53.26,7.54 58.34,7.54 | 38.02,7.54 43.1,7.54
S$23  (1 unrouted)
  Bottom 1.676: 83.74,10.08 88.82,10.08 | 68.5,10.08 73.58,10.08
S$24  (1 unrouted)
  Bottom 1.676: 83.74,7.54 88.82,7.54 | 68.5,7.54 73.58,7.54
S$26
  Top 1.676: 71.04,38.02 71.04,48.18
S$27
  Top 0.305: 68.5,48.18 68.18,47.86
  Top 1.676: 68.5,38.02 68.5,48.18
S$29
  Top 0.305: 57.7,36.43 58.34,37.07 58.34,37.7 58.66,38.02
S$30
  Top 0.406: 81.52,42.78 E$7.3
S$32
  Top 0.305: 57.7,34.53 64.06,34.53 65.96,36.43 65.96,37.7
S$33
  Top 0.305: 57.7,33.89 65.01,33.89 65.96,32.94 65.96,30.72
S$34  (3 unrouted)
  Bottom 0.406: 104.69,58.34 100.89,54.53 100.89,50.09 98.98,48.18 | 111.05,55.8 104.69,55.8 102.79,53.9 102.79,50.72 104.06,49.45 104.06,48.18 | 105.97,51.99 107.87,51.99 109.14,50.72 109.14,48.18
  Bottom 1.676: 109.14,38.02 109.14,48.18 | 98.98,38.02 98.98,48.18 | 96.44,38.02 96.44,48.18 | 104.06,38.02 104.06,48.18
S$35
  Top 0.406: 88.82,42.78 89.14,42.47
S$37
  Top 0.406: 90.41,36.11 92,36.11 93.58,37.7
S$38
  Bottom 0.406: 106.6,12.62 111.05,12.62 111.05,16.43 104.06,20.24
  Bottom 1.676: 104.06,20.24 104.06,30.4
S$39
  Top 0.305: 96.12,31.04 96.44,30.72
S$40
  Top 0.406: 30.4,19.61 31.67,18.34 31.67,16.43 31.04,15.79 29.77,15.79
  Top 0.61: 29.77,15.79 28.5,14.53 27.23,14.53
S$41
  Top 0.406: 20.88,14.53 20.88,11.98 25.32,11.98
  Top 0.61: 25.32,13.26 25.32,11.98 27.67,11.98
S$42  (30 unrouted)
  Top 0.305: 90.09,39.92 89.45,39.92 88.82,40.56 88.19,40.56 86.28,42.47 86.28,43.1 | 90.72,38.66 91.04,38.66 91.55,39.16 91.55,40.62 90.92,41.26 90.66,41.26 88.82,43.1 | 90.72,37.38 91.17,37.38 92.31,37.89 92.31,42.02 91.68,42.66 91.68,42.78 91.36,43.1 | 81.83,39.92 83.74,42.47 83.74,43.1 | 79.3,38.66 78.91,38.66 78.47,39.1 78.47,40.75 79.11,41.39 80.12,41.39 81.2,42.47 81.2,43.1 | 79.3,37.38 78.34,37.38 77.64,38.08 77.64,41.96 78.66,43.1 | 79.3,31.04 78.66,31.04 77.71,29.77 77.71,25.95 78.66,25.32 | 79.3,29.77 78.47,29.19 78.47,27.23 79.3,26.72 80.56,26.72 81.2,25.95 81.2,25.32 | 82.47,28.5 83.74,27.23 83.74,25.32 | 90.72,31.04 91.36,31.04 92.44,29.96 92.44,26.14 91.36,25.32 | 90.72,29.77 91.74,29.32 91.74,27.23 90.79,26.72 89.52,26.72 88.82,25.95 88.82,25.32 | 86.28,25.32 86.92,25.95 86.92,27.86 87.55,28.5
  Top 0.406: 77.39,14.53 77.39,18.34 78.66,19.61 78.66,20.24 | 91.36,20.24 91.36,19.61 | 79.93,53.26 81.2,53.26 82.47,51.99 82.47,50.09 81.2,48.81 81.2,48.18
  Top 1.676: 78.66,20.24 78.66,25.32 | 81.2,20.24 81.2,25.32 | 83.74,20.24 83.74,25.32 | 86.28,20.24 86.28,25.32 | 88.82,20.24 88.82,25.32 | 91.36,25.32 91.36,20.24 | 91.36,43.1 91.36,48.18 | 88.82,43.1 88.82,48.18 | 86.28,43.1 86.28,48.18 | 83.74,43.1 83.74,48.18 | 81.2,48.18 81.2,43.1 | 78.66,43.1 78.66,48.18 | 58.34,38.02 58.34,43.1 | 55.8,38.02 55.8,43.1 | 53.26,38.02 53.26,43.1 | 50.72,38.02 50.72,43.1 | 48.18,38.02 48.18,43.1 | 45.64,38.02 45.64,43.1 | 43.1,38.02 43.1,43.1
  Bottom 1.676: 78.66,20.24 78.66,25.32 | 81.2,20.24 81.2,25.32 | 83.74,20.24 83.74,25.32 | 86.28,20.24 86.28,25.32 | 88.82,20.24 88.82,25.32 | 91.36,25.32 91.36,20.24 | 91.36,43.1 91.36,48.18 | 88.82,43.1 88.82,48.18 | 86.28,43.1 86.28,48.18 | 83.74,43.1 83.74,48.18 | 81.2,48.18 81.2,43.1 | 78.66,43.1 78.66,48.18
S$43
  Top 0.406: E$14.3 81.52,25.64
S$45
  Top 0.813: 57.7,47.55 55.8,47.55 E$17.1
S$46
  Top 0.406: 53.26,53.26 53.26,56.12 55.67,56.12
  Top 0.813: 56.44,53.26 53.26,53.26 53.26,42.47
S$47  (1 unrouted)
  Top 0.406: 96.44,38.02 96.44,37.38 94.85,35.8 92.63,34.84 90.09,34.84 | 98.98,48.81 100.25,50.09 100.25,51.99 98.34,53.9
  Top 0.61: 98.98,48.18 98.98,48.81
  Top 1.676: 98.98,38.02 98.98,48.18 | 96.44,38.02 96.44,48.18
S$48
  Top 0.406: 71.04,11.98 71.04,13.26
S$49
  Top 0.406: 65.33,19.61 65.33,18.97 64.69,18.34 64.69,15.16 65.33,14.53
S$50
  Top 0.406: 81.2,19.61 82.47,18.34 82.47,14.53
S$51
  Top 0.406: 86.28,11.98 86.28,12.62 85.64,13.26 83.74,13.26
S$52
  Top 0.406: 93.27,48.81 93.27,49.45 92.63,50.09 92.63,53.9 93.27,54.53
S$53
  Top 0.406: 90.72,15.16 90.72,14.53 91.36,13.89
S$54
  Top 0.406: 93.27,20.24 93.27,19.61 92.63,18.97 92.63,15.16 92,14.53
S$55
  Top 0.406: 43.1,13.89 43.1,12.62
S$56
  Top 0.406: 79.61,34.84 74.53,34.84 73.58,36.43 73.58,38.02
  Top 1.676: 73.58,38.02 73.58,48.18
S$57
  Top 0.61: 7.54,56.12 E$19.1
S$58
  Top 0.61: 7.86,55.8 10.71,55.8
S$59
  Top 0.406: 43.1,16.43 43.1,17.06
S$61
  Top 0.406: 86.28,56.44 86.28,55.16 86.92,54.53 90.09,54.53
S$63
  Top 0.254: 51.99,35.16 53.26,34.97
S$64
  Top 0.254: 52.94,34.46 51.99,34.53
S$65
  Top 0.254: 51.99,33.89 52.94,33.93
S$66
  Top 0.254: 53.07,33.45 51.99,33.26
S$67
  Top 0.254: 57.07,33.26 56.12,33.45
S$68
  Top 0.254: 57.39,33.89 56.12,33.96
S$69
  Top 0.254: 57.39,34.53 56.12,34.46
S$70
  Top 0.254: 57.07,35.16 56.05,34.97
S$79
  Top 0.61: 22.78,48.5 22.78,50.72
S$80
  Top 0.61: 12.3,48.18 12.62,48.5
S$81
  Top 0.406: 38.02,11.98 38.02,10.71
S$82
  Top 0.61: 7.54,52.62 10.08,52.62
S$83
  Top 0.406: 22.78,51.35 25.32,52.62
S$86
  Top 0.406: 55.8,11.98 55.8,13.26
S$87
  Top 1.676: 7.54,20.24 7.54,30.4
S$88
  Top 0.406: 58.34,11.98 58.34,10.71
S$89
  Top 0.406: 58.34,15.79 arc-135 58.34,19.61
S$90
  Top 0.61: 7.54,48.5 7.54,52.62
S$91  (3 unrouted)
  Top 0.61: 7.22,11.67 7.22,11.03 8.18,10.08 12.62,10.08
  Top 1.676: 27.86,10.08 38.02,10.08 | 27.86,7.54 38.02,7.54 | 12.62,7.54 22.78,7.54 | 12.62,10.08 22.78,10.08
S$93
  Top 0.61: 11.98,52.31 11.98,51.04 12.62,50.09 12.62,48.81

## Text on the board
Top: 1 | 5 | 10 | 15 | 20 | 25 | 30 | A | B | C | D | 30062012 | E | A | E | F | G | H | MICHAEL5.net | I | J | 60 | 55 | 50 | 45 | 40 | 35 | 30
Bottom: 3006012 | MICHAEL5.net
tStop: 10 | 1 | 5 | 15 | 20 | 25 | 30 | A | B | C | D | E | F | G | H | I | J | 60 | 55 | 50 | 45 | 40 | 35 | 30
